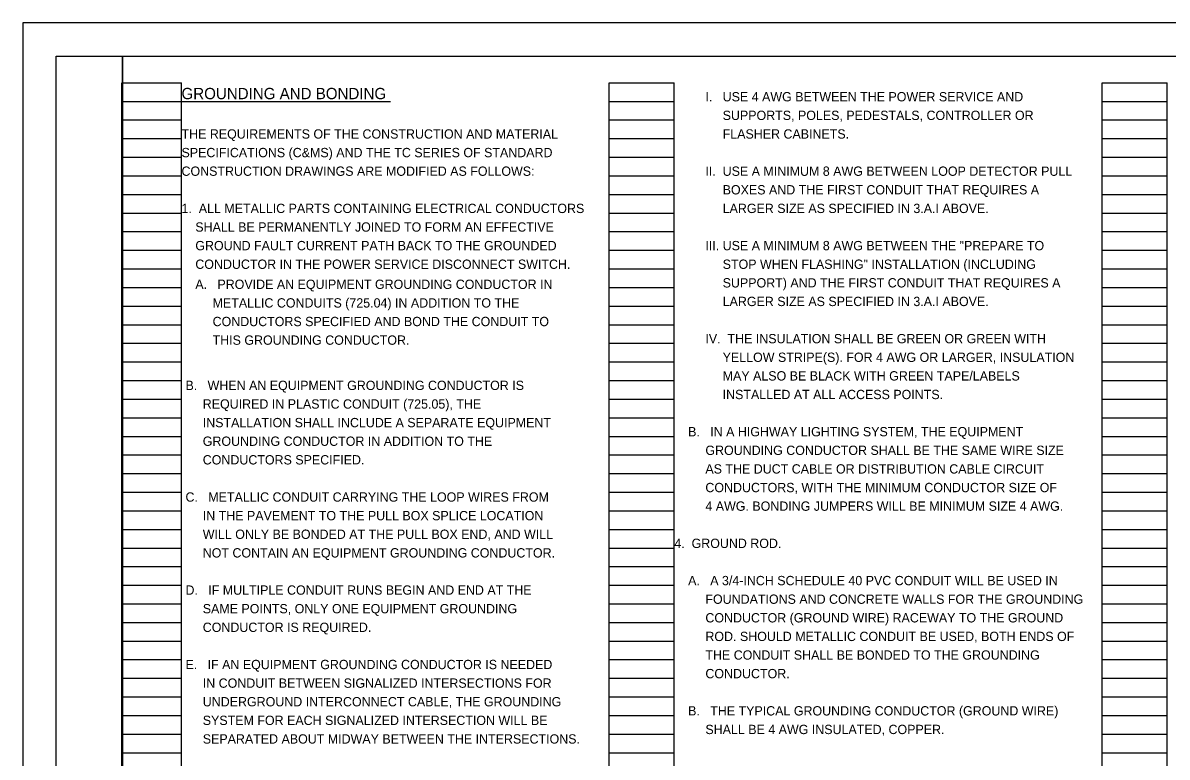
# Model space of a CAD drawing. Extents: x -57 to 90, y -15 to 48.
# Drawn here: x 55.69 to 72.92, y 36.46 to 47.51 of the extents above; entities that cross this region are included whole.
import ezdxf

# ---------------------------------------------------------------- set-up
doc = ezdxf.new("R2010")
doc.units = 0
for name, color, linetype in [('SH_Border', 7, 'Continuous'), ('SH_Cut_Line', 7, 'Continuous'), ('SH_Data', 7, 'Continuous'), ('SH_Text', 7, 'Continuous')]:
    doc.layers.add(name, color=color, linetype=linetype)

msp = doc.modelspace()

# ---------------------------------------------------------------- linework, layer by layer
at = {"layer": 'SH_Border'}
for points in [[(56.188, 47.006), (57.188, 47.006), (57.188, 26.006), (56.188, 26.006)], [(57.188, 47.006), (89.188, 47.006), (89.188, 26.006), (57.188, 26.006)]]:
    msp.add_lwpolyline(points, close=True, dxfattribs=at)
at = {"layer": 'SH_Cut_Line'}
msp.add_lwpolyline([(55.688, 25.506), (89.688, 25.506), (89.688, 47.506), (55.688, 47.506)], close=True, dxfattribs=at)
at = {"layer": 'SH_Data'}
for p, q in [((57.176, 26.445), (57.176, 46.605)), ((57.176, 46.605), (58.076, 46.605)), ((58.076, 26.445), (58.076, 46.605)), ((64.516, 26.445), (64.516, 46.605)), ((64.516, 46.605), (65.496, 46.605)), ((65.496, 26.445), (65.496, 46.605)), ((71.936, 26.445), (71.936, 46.605)), ((71.936, 46.605), (72.916, 46.605)), ((72.916, 26.445), (72.916, 46.605)), ((57.176, 46.325), (58.076, 46.325)), ((64.516, 46.325), (65.496, 46.325)), ((71.936, 46.325), (72.916, 46.325)), ((57.176, 46.045), (58.076, 46.045)), ((64.516, 46.045), (65.496, 46.045)), ((71.936, 46.045), (72.916, 46.045)), ((57.176, 45.765), (58.076, 45.765)), ((64.516, 45.765), (65.496, 45.765)), ((71.936, 45.765), (72.916, 45.765)), ((57.176, 45.485), (58.076, 45.485)), ((64.516, 45.485), (65.496, 45.485)), ((71.936, 45.485), (72.916, 45.485)), ((57.176, 45.205), (58.076, 45.205)), ((64.516, 45.205), (65.496, 45.205)), ((71.936, 45.205), (72.916, 45.205)), ((57.176, 44.925), (58.076, 44.925)), ((64.516, 44.925), (65.496, 44.925)), ((71.936, 44.925), (72.916, 44.925)), ((57.176, 44.645), (58.076, 44.645)), ((64.516, 44.645), (65.496, 44.645)), ((71.936, 44.645), (72.916, 44.645)), ((57.176, 44.365), (58.076, 44.365)), ((64.516, 44.365), (65.496, 44.365)), ((71.936, 44.365), (72.916, 44.365)), ((57.176, 44.085), (58.076, 44.085)), ((64.516, 44.085), (65.496, 44.085)), ((71.936, 44.085), (72.916, 44.085)), ((57.176, 43.805), (58.076, 43.805)), ((64.516, 43.805), (65.496, 43.805)), ((71.936, 43.805), (72.916, 43.805)), ((57.176, 43.525), (58.076, 43.525)), ((64.516, 43.525), (65.496, 43.525)), ((71.936, 43.525), (72.916, 43.525)), ((57.176, 43.245), (58.076, 43.245)), ((64.516, 43.245), (65.496, 43.245)), ((71.936, 43.245), (72.916, 43.245)), ((57.176, 42.965), (58.076, 42.965)), ((64.516, 42.965), (65.496, 42.965)), ((71.936, 42.965), (72.916, 42.965)), ((57.176, 42.685), (58.076, 42.685)), ((64.516, 42.685), (65.496, 42.685)), ((71.936, 42.685), (72.916, 42.685)), ((57.176, 42.405), (58.076, 42.405)), ((64.516, 42.405), (65.496, 42.405)), ((71.936, 42.405), (72.916, 42.405)), ((57.176, 42.125), (58.076, 42.125)), ((64.516, 42.125), (65.496, 42.125)), ((71.936, 42.125), (72.916, 42.125)), ((57.176, 41.845), (58.076, 41.845)), ((64.516, 41.845), (65.496, 41.845)), ((71.936, 41.845), (72.916, 41.845)), ((57.176, 41.565), (58.076, 41.565)), ((64.516, 41.565), (65.496, 41.565)), ((71.936, 41.565), (72.916, 41.565)), ((57.176, 41.285), (58.076, 41.285)), ((64.516, 41.285), (65.496, 41.285)), ((71.936, 41.285), (72.916, 41.285)), ((57.176, 41.005), (58.076, 41.005)), ((64.516, 41.005), (65.496, 41.005)), ((71.936, 41.005), (72.916, 41.005)), ((57.176, 40.725), (58.076, 40.725)), ((64.516, 40.725), (65.496, 40.725)), ((71.936, 40.725), (72.916, 40.725)), ((57.176, 40.445), (58.076, 40.445)), ((64.516, 40.445), (65.496, 40.445)), ((71.936, 40.445), (72.916, 40.445)), ((57.176, 40.165), (58.076, 40.165)), ((64.516, 40.165), (65.496, 40.165)), ((71.936, 40.165), (72.916, 40.165)), ((57.176, 39.885), (58.076, 39.885)), ((64.516, 39.885), (65.496, 39.885)), ((71.936, 39.885), (72.916, 39.885)), ((57.176, 39.605), (58.076, 39.605)), ((64.516, 39.605), (65.496, 39.605)), ((71.936, 39.605), (72.916, 39.605)), ((57.176, 39.325), (58.076, 39.325)), ((64.516, 39.325), (65.496, 39.325)), ((71.936, 39.325), (72.916, 39.325)), ((57.176, 39.045), (58.076, 39.045)), ((64.516, 39.045), (65.496, 39.045)), ((71.936, 39.045), (72.916, 39.045)), ((57.176, 38.765), (58.076, 38.765)), ((64.516, 38.765), (65.496, 38.765)), ((71.936, 38.765), (72.916, 38.765)), ((57.176, 38.485), (58.076, 38.485)), ((64.516, 38.485), (65.496, 38.485)), ((71.936, 38.485), (72.916, 38.485)), ((57.176, 38.205), (58.076, 38.205)), ((64.516, 38.205), (65.496, 38.205)), ((71.936, 38.205), (72.916, 38.205)), ((57.176, 37.925), (58.076, 37.925)), ((64.516, 37.925), (65.496, 37.925)), ((71.936, 37.925), (72.916, 37.925)), ((57.176, 37.645), (58.076, 37.645)), ((64.516, 37.645), (65.496, 37.645)), ((71.936, 37.645), (72.916, 37.645)), ((57.176, 37.365), (58.076, 37.365)), ((64.516, 37.365), (65.496, 37.365)), ((71.936, 37.365), (72.916, 37.365)), ((57.176, 37.085), (58.076, 37.085)), ((64.516, 37.085), (65.496, 37.085)), ((71.936, 37.085), (72.916, 37.085)), ((57.176, 36.805), (58.076, 36.805)), ((64.516, 36.805), (65.496, 36.805)), ((71.936, 36.805), (72.916, 36.805)), ((57.176, 36.525), (58.076, 36.525)), ((64.516, 36.525), (65.496, 36.525)), ((71.936, 36.525), (72.916, 36.525))]:
    msp.add_line(p, q, dxfattribs=at)
at = {"layer": 'SH_Text'}
msp.add_line((58.076, 46.325), (61.222, 46.325), dxfattribs=at)

# ---------------------------------------------------------------- texts
for s, height, p in [('GROUNDING AND BONDING', 0.17, (58.076, 46.358)), ('         I.   USE 4 AWG BETWEEN THE POWER SERVICE AND', 0.14, (65.496, 46.325)), ('              SUPPORTS, POLES, PEDESTALS, CONTROLLER OR', 0.14, (65.496, 46.045)), ('THE REQUIREMENTS OF THE CONSTRUCTION AND MATERIAL', 0.14, (58.076, 45.765)), ('              FLASHER CABINETS.', 0.14, (65.496, 45.765)), ('SPECIFICATIONS (C&MS) AND THE TC SERIES OF STANDARD', 0.14, (58.076, 45.485)), ('CONSTRUCTION DRAWINGS ARE MODIFIED AS FOLLOWS:', 0.14, (58.076, 45.205)), ('         II.  USE A MINIMUM 8 AWG BETWEEN LOOP DETECTOR PULL', 0.14, (65.496, 45.205)), ('              BOXES AND THE FIRST CONDUIT THAT REQUIRES A', 0.14, (65.496, 44.925)), ('1.  ALL METALLIC PARTS CONTAINING ELECTRICAL CONDUCTORS', 0.14, (58.076, 44.645)), ('              LARGER SIZE AS SPECIFIED IN 3.A.I ABOVE.', 0.14, (65.496, 44.645)), ('    SHALL BE PERMANENTLY JOINED TO FORM AN EFFECTIVE', 0.14, (58.076, 44.365)), ('    GROUND FAULT CURRENT PATH BACK TO THE GROUNDED', 0.14, (58.076, 44.085)), ('         III. USE A MINIMUM 8 AWG BETWEEN THE "PREPARE TO', 0.14, (65.496, 44.085)), ('    CONDUCTOR IN THE POWER SERVICE DISCONNECT SWITCH.', 0.14, (58.076, 43.805)), ('              STOP WHEN FLASHING" INSTALLATION (INCLUDING', 0.14, (65.496, 43.805)), ('    A.   PROVIDE AN EQUIPMENT GROUNDING CONDUCTOR IN', 0.14, (58.076, 43.503)), ('              SUPPORT) AND THE FIRST CONDUIT THAT REQUIRES A', 0.14, (65.496, 43.525)), ('         METALLIC CONDUITS (725.04) IN ADDITION TO THE', 0.14, (58.076, 43.223)), ('              LARGER SIZE AS SPECIFIED IN 3.A.I ABOVE.', 0.14, (65.496, 43.245)), ('         CONDUCTORS SPECIFIED AND BOND THE CONDUIT TO', 0.14, (58.076, 42.943)), ('         THIS GROUNDING CONDUCTOR.', 0.14, (58.076, 42.663)), ('         IV.  THE INSULATION SHALL BE GREEN OR GREEN WITH', 0.14, (65.496, 42.685)), ('              YELLOW STRIPE(S). FOR 4 AWG OR LARGER, INSULATION', 0.14, (65.496, 42.405)), ('              MAY ALSO BE BLACK WITH GREEN TAPE/LABELS', 0.14, (65.496, 42.125)), ('    B.   WHEN AN EQUIPMENT GROUNDING CONDUCTOR IS', 0.14, (57.928, 41.982)), ('              INSTALLED AT ALL ACCESS POINTS.', 0.14, (65.496, 41.845)), ('         REQUIRED IN PLASTIC CONDUIT (725.05), THE', 0.14, (57.928, 41.702)), ('         INSTALLATION SHALL INCLUDE A SEPARATE EQUIPMENT', 0.14, (57.928, 41.422)), ('    B.   IN A HIGHWAY LIGHTING SYSTEM, THE EQUIPMENT', 0.14, (65.496, 41.285)), ('         GROUNDING CONDUCTOR IN ADDITION TO THE', 0.14, (57.928, 41.142)), ('         GROUNDING CONDUCTOR SHALL BE THE SAME WIRE SIZE', 0.14, (65.496, 41.005)), ('         CONDUCTORS SPECIFIED.', 0.14, (57.928, 40.862)), ('         AS THE DUCT CABLE OR DISTRIBUTION CABLE CIRCUIT', 0.14, (65.496, 40.725)), ('         CONDUCTORS, WITH THE MINIMUM CONDUCTOR SIZE OF', 0.14, (65.496, 40.445)), ('    C.   METALLIC CONDUIT CARRYING THE LOOP WIRES FROM', 0.14, (57.928, 40.302)), ('         IN THE PAVEMENT TO THE PULL BOX SPLICE LOCATION', 0.14, (57.928, 40.022)), ('         4 AWG. BONDING JUMPERS WILL BE MINIMUM SIZE 4 AWG.', 0.14, (65.496, 40.165)), ('         WILL ONLY BE BONDED AT THE PULL BOX END, AND WILL', 0.14, (57.928, 39.742)), ('4.  GROUND ROD.', 0.14, (65.496, 39.605)), ('         NOT CONTAIN AN EQUIPMENT GROUNDING CONDUCTOR.', 0.14, (57.928, 39.462)), ('    A.   A 3/4-INCH SCHEDULE 40 PVC CONDUIT WILL BE USED IN', 0.14, (65.496, 39.045)), ('    D.   IF MULTIPLE CONDUIT RUNS BEGIN AND END AT THE', 0.14, (57.928, 38.902)), ('         FOUNDATIONS AND CONCRETE WALLS FOR THE GROUNDING', 0.14, (65.496, 38.765)), ('         SAME POINTS, ONLY ONE EQUIPMENT GROUNDING', 0.14, (57.928, 38.622)), ('         CONDUCTOR (GROUND WIRE) RACEWAY TO THE GROUND', 0.14, (65.496, 38.485)), ('         CONDUCTOR IS REQUIRED.', 0.14, (57.928, 38.342)), ('         ROD. SHOULD METALLIC CONDUIT BE USED, BOTH ENDS OF', 0.14, (65.496, 38.205)), ('    E.   IF AN EQUIPMENT GROUNDING CONDUCTOR IS NEEDED', 0.14, (57.928, 37.782)), ('         THE CONDUIT SHALL BE BONDED TO THE GROUNDING', 0.14, (65.496, 37.925)), ('         CONDUCTOR.', 0.14, (65.496, 37.645)), ('         IN CONDUIT BETWEEN SIGNALIZED INTERSECTIONS FOR', 0.14, (57.928, 37.502)), ('         UNDERGROUND INTERCONNECT CABLE, THE GROUNDING', 0.14, (57.928, 37.222)), ('    B.   THE TYPICAL GROUNDING CONDUCTOR (GROUND WIRE)', 0.14, (65.496, 37.085)), ('         SYSTEM FOR EACH SIGNALIZED INTERSECTION WILL BE', 0.14, (57.928, 36.942)), ('         SHALL BE 4 AWG INSULATED, COPPER.', 0.14, (65.496, 36.805)), ('         SEPARATED ABOUT MIDWAY BETWEEN THE INTERSECTIONS.', 0.14, (57.928, 36.662))]:
    msp.add_text(s, height=height, dxfattribs=at).set_placement(p)

doc.saveas('drawing.dxf')
